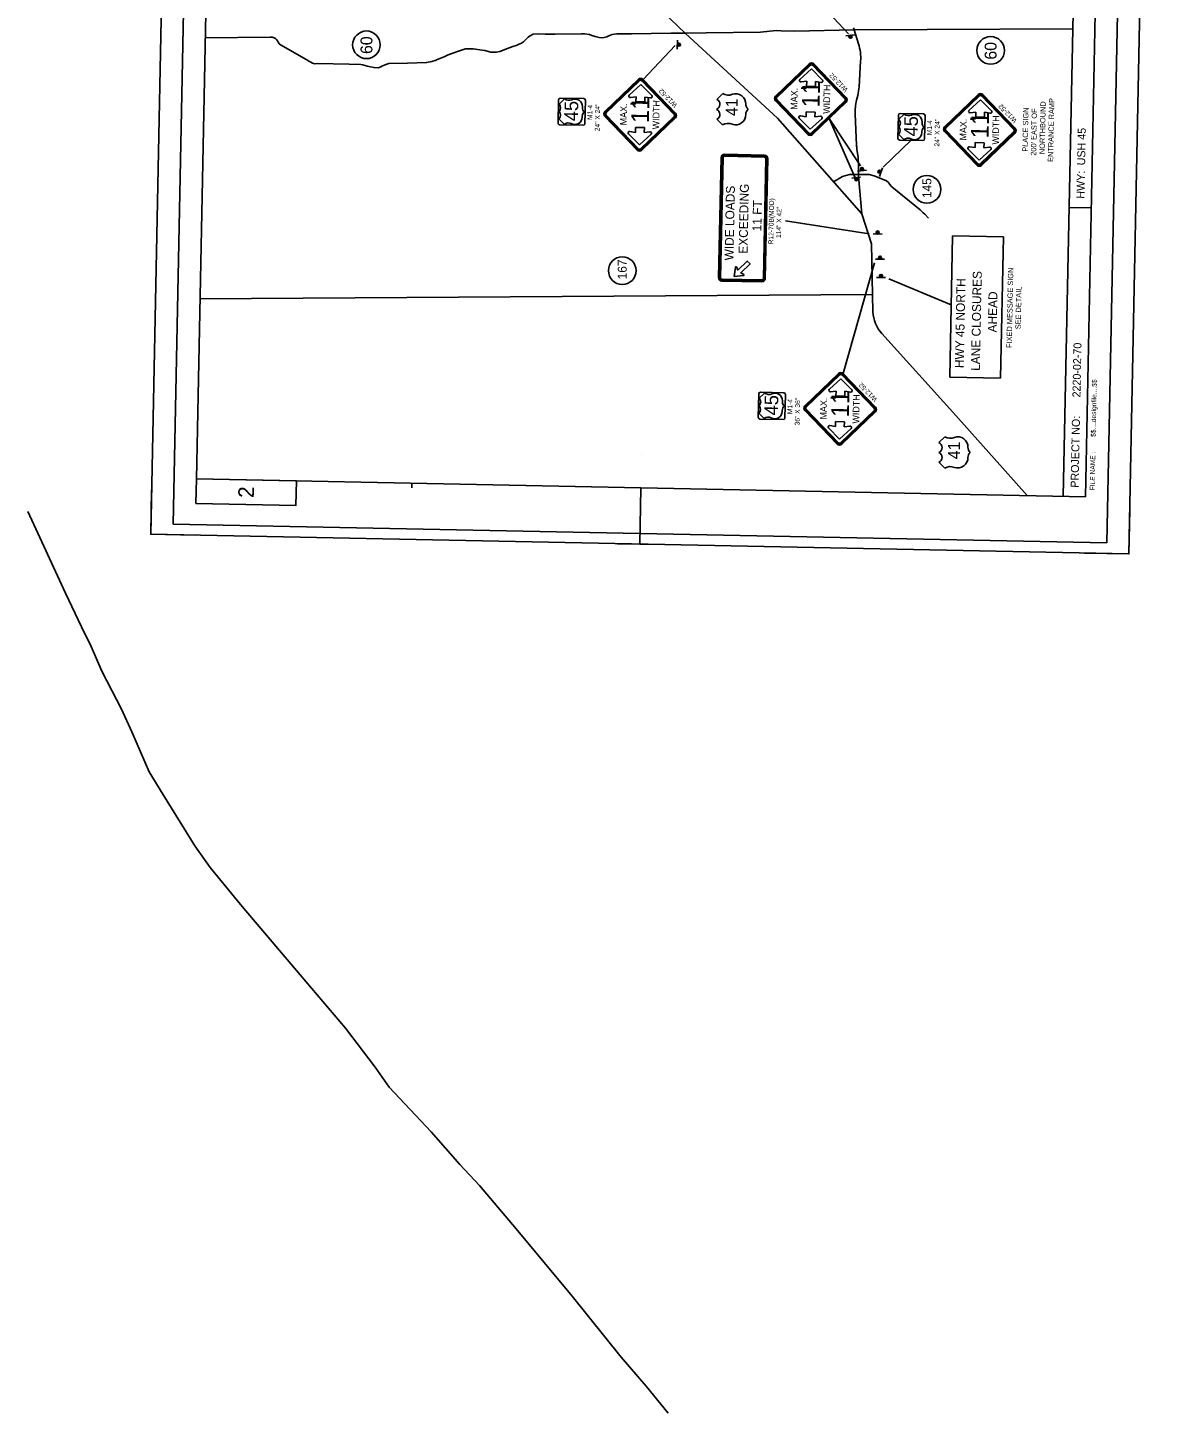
# Model space of a CAD drawing. Extents: x 2191881 to 2513407, y 347956 to 627029.
# Drawn here: x 2398895 to 2513407, y 347956 to 488157 of the extents above; entities that cross this region are included whole.
import ezdxf

# ---------------------------------------------------------------- set-up
doc = ezdxf.new("R2010")
doc.units = 0
for name, color, linetype in [('CA-TEXT', 7, 'Continuous'), ('Level 1', 7, 'Continuous'), ('Level 15', 7, 'Continuous'), ('Level 52', 7, 'Continuous'), ('P_RDWY_Text', 7, 'Continuous'), ('P_SGN_Cell', 7, 'Continuous'), ('P_TC', 7, 'Continuous'), ('PLT_Sheet_Border', 7, 'Continuous')]:
    doc.layers.add(name, color=color, linetype=linetype)

msp = doc.modelspace()

# ---------------------------------------------------------------- linework, layer by layer
at = {"layer": 'Level 1'}
msp.add_line((2458960, 353650), (2459055, 353554), dxfattribs=at)
for points in [[(2411176, 412871), (2409445, 416925), (2408371, 419215), (2406399, 423062), (2405327, 425534), (2404342, 427549), (2402731, 430937), (2398895, 439215)], [(2459055, 353554), (2458960, 353650), (2453998, 359805), (2448312, 366604), (2444611, 371014), (2442623, 373130), (2439733, 376438), (2435486, 380945), (2434044, 382964), (2431069, 386912), (2426465, 392333), (2420598, 399225), (2417349, 403176), (2415818, 405378), (2412581, 410605), (2411176, 412871)], [(2463712, 347956), (2461488, 350710), (2458960, 353650)]]:
    msp.add_lwpolyline(points, dxfattribs=at)
at = {"layer": 'Level 52'}
for p, q in [((2415960, 442501), (2418814, 584223)), ((2503692, 440734), (2506546, 582456)), ((2505942, 440689), (2508796, 582410)), ((2506530, 469933), (2504281, 469979)), ((2492210, 452806), (2492497, 467085)), ((2492497, 467085), (2497640, 466981)), ((2497352, 452703), (2497640, 466981)), ((2492210, 452806), (2497352, 452703)), ((2461019, 444970), (2461019, 444970)), ((2505942, 440689), (2415960, 442501)), ((2437780, 442062), (2437771, 441612)), ((2411346, 436901), (2411437, 441400)), ((2460836, 435904), (2460951, 441595)), ((2510326, 434907), (2510417, 439406)), ((2415845, 436810), (2411346, 436901)), ((2463086, 435859), (2458586, 435949)), ((2510326, 434907), (2505827, 434998))]:
    msp.add_line(p, q, dxfattribs=at)
msp.add_lwpolyline([(2415960, 442501), (2415910, 440027), (2426033, 439823), (2426083, 442297)], close=True, dxfattribs=at)
at = {"layer": 'P_RDWY_Text'}
for p, q in [((2465460, 487557), (2456867, 495857)), ((2476911, 492930), (2481949, 487544)), ((2476502, 487820), (2482538, 487931)), ((2482538, 487931), (2504645, 488037)), ((2482970, 486531), (2482538, 487931)), ((2465399, 487616), (2467564, 487634)), ((2474770, 478999), (2465460, 487556)), ((2467564, 487634), (2473055, 487719)), ((2473055, 487719), (2474646, 487864)), ((2474646, 487864), (2475155, 487837)), ((2475155, 487837), (2476502, 487820)), ((2433175, 486427), (2433175, 486427)), ((2461181, 482931), (2464428, 486351)), ((2496339, 485857), (2496339, 485857)), ((2483028, 482188), (2483182, 484758)), ((2468626, 480897), (2469223, 481495)), ((2482776, 480812), (2482897, 481312)), ((2470036, 479942), (2470036, 479942)), ((2468617, 478910), (2469214, 478313)), ((2483308, 469309), (2474770, 478999)), ((2480013, 478983), (2483175, 474166)), ((2480013, 478983), (2482609, 473023)), ((2482774, 476281), (2482640, 479422)), ((2485477, 474045), (2488300, 476763)), ((2482919, 475010), (2482810, 475859)), ((2482957, 473551), (2482959, 474361)), ((2481337, 473093), (2480447, 472557)), ((2482057, 473306), (2481337, 473093)), ((2483591, 473308), (2482057, 473306)), ((2483308, 469309), (2482974, 473131)), ((2489894, 471798), (2489894, 471798)), ((2484047, 467295), (2475591, 468618)), ((2484276, 466292), (2483309, 469309)), ((2484276, 466292), (2484412, 459415)), ((2484603, 464368), (2481422, 453164)), ((2459059, 463574), (2459059, 463574)), ((2492357, 460121), (2486044, 462734)), ((2484378, 461163), (2416327, 460717)), ((2492802, 448917), (2485332, 457203)), ((2492802, 448917), (2500028, 440808)), ((2491108, 446176), (2491706, 446773)), ((2492519, 445221), (2492519, 445221)), ((2491100, 444189), (2491697, 443591))]:
    msp.add_line(p, q, dxfattribs=at)
msp.add_lwpolyline([(2411346, 436901), (2414427, 589870), (2513407, 587876), (2510326, 434907)], close=True, dxfattribs=at)
for points in [[(2431411, 484483), (2428206, 484519), (2427964, 484517), (2427710, 484578), (2427531, 484661), (2427340, 484766), (2427139, 484923), (2424481, 486435), (2424343, 486539), (2424247, 486697), (2424161, 486834), (2424086, 486961), (2423969, 487076), (2423821, 487149), (2423621, 487190), (2423431, 487198), (2416859, 487135)], [(2431411, 484483), (2432595, 484439), (2432821, 484409), (2433256, 484281), (2433582, 484201), (2433942, 484114), (2434351, 484086), (2434468, 484121), (2434700, 484215), (2434716, 484249), (2435222, 484472), (2435447, 484525), (2437323, 484565), (2439257, 484622), (2439781, 484729), (2440221, 484876), (2440254, 484910), (2440595, 485031), (2440760, 485116), (2441026, 485219), (2441432, 485416), (2442379, 485745), (2443210, 486013), (2443985, 486023), (2444871, 485884), (2445139, 485837), (2445766, 485670), (2446316, 485677), (2446666, 485748), (2446957, 485852), (2447023, 485894), (2447446, 486049), (2447986, 486256), (2448426, 486403), (2448525, 486471), (2448874, 486592), (2449064, 486728), (2449534, 487209), (2449666, 487310), (2450056, 487490), (2450580, 487547), (2451273, 487506), (2452191, 487492), (2452274, 487493), (2454951, 487526)], [(2454951, 487526), (2455226, 487530), (2455752, 487470), (2455987, 487373), (2456330, 487260), (2456726, 487155), (2456954, 487125), (2457224, 487171), (2457498, 487241), (2457714, 487327), (2458054, 487465), (2458529, 487538), (2459715, 487539)], [(2459715, 487539), (2459997, 487542), (2463982, 487606), (2465414, 487601)], [(2483591, 473308), (2484050, 473288), (2484560, 473178), (2485817, 472669), (2486036, 472455), (2486096, 472322), (2486350, 472050), (2489223, 469719), (2489484, 469464), (2489502, 469414), (2489670, 469283), (2490065, 468893)]]:
    msp.add_lwpolyline(points, dxfattribs=at)
for centre in [(2433175, 486427), (2496339, 485857), (2489894, 471798), (2459059, 463574)]:
    msp.add_circle(centre, 1398, dxfattribs=at)
for centre, radius, start, end in [((2487316, 489403), 5000, 194.43825, 197.12806), ((2465460, 487557), 1, 225.991, 227.41449), ((2478191, 485058), 5000, 356.56138, 17.12806), ((2468395, 480400), 548, 293.11923, 65.07067), ((2469779, 482361), 1030, 237.31366, 294.1957), ((2470534, 480447), 1030, 357.80954, 108.90524), ((2478037, 482487), 5000, 346.39961, 356.56138), ((2468395, 479392), 548, 294.92933, 66.88077), ((2472309, 479363), 755, 133.77282, 178.75675), ((2472318, 480445), 755, 181.24325, 225.27704), ((2487635, 479636), 5000, 166.39961, 182.44488), ((2469770, 477446), 1030, 65.8043, 122.68634), ((2470525, 479360), 1030, 251.09476, 2.19046), ((2474770, 478999), 1, 41.38328, 47.41449), ((2487770, 476494), 5000, 182.44488, 187.30106), ((2477959, 474375), 5000, 359.83776, 7.30106), ((2487957, 473536), 5000, 179.83776, 184.64635), ((2483308, 469308), 1, 17.78377, 41.38328), ((2488317, 459741), 3918, 184.76287, 220.36638), ((2490877, 445679), 548, 293.11923, 65.07067), ((2492262, 447640), 1030, 237.31366, 294.1957), ((2493016, 445726), 1030, 357.80954, 108.90524), ((2490877, 444671), 548, 294.92933, 66.88077), ((2493007, 444639), 1030, 251.09476, 2.19046), ((2494792, 444642), 755, 133.77282, 178.75675), ((2494801, 445724), 755, 181.24325, 225.27704), ((2492253, 442725), 1030, 65.8043, 122.68634)]:
    msp.add_arc(centre, radius, start, end, dxfattribs=at)
at = {"layer": 'P_SGN_Cell'}
for p, q in [((2477046, 482910), (2478206, 483980)), ((2478206, 483980), (2479322, 482864)), ((2459775, 481336), (2460935, 482406)), ((2460935, 482406), (2462051, 481290)), ((2477732, 482733), (2477158, 482667)), ((2477721, 482232), (2477731, 482733)), ((2478631, 482715), (2478621, 482214)), ((2479201, 482625), (2478630, 482715)), ((2453227, 480957), (2452681, 480432)), ((2452799, 481030), (2455161, 480982)), ((2460461, 481159), (2459887, 481093)), ((2460450, 480658), (2460460, 481159)), ((2461360, 481141), (2461350, 480640)), ((2461930, 481051), (2461359, 481141)), ((2478621, 482214), (2477721, 482232)), ((2452579, 478503), (2452626, 480865)), ((2455031, 480063), (2455033, 480170)), ((2455302, 479629), (2455278, 478448)), ((2455326, 480810), (2455302, 479629)), ((2455326, 480810), (2455326, 480810)), ((2461350, 480640), (2460450, 480658)), ((2477659, 479144), (2477669, 479645)), ((2477669, 479645), (2478569, 479627)), ((2478569, 479627), (2478558, 479126)), ((2487174, 479486), (2489536, 479439)), ((2494150, 479792), (2495310, 480862)), ((2494836, 479615), (2494262, 479549)), ((2494825, 479114), (2494835, 479615)), ((2495310, 480863), (2496426, 479746)), ((2495735, 479597), (2495725, 479096)), ((2496305, 479508), (2495734, 479597)), ((2452650, 478932), (2453175, 478386)), ((2455106, 478283), (2452744, 478330)), ((2455012, 479099), (2455014, 479206)), ((2478083, 477879), (2476967, 478995)), ((2477089, 479234), (2477660, 479144)), ((2479243, 478949), (2478083, 477879)), ((2478558, 479126), (2479132, 479192)), ((2486954, 476959), (2487002, 479321)), ((2487602, 479413), (2487056, 478888)), ((2489406, 478520), (2489408, 478627)), ((2489677, 478085), (2489653, 476904)), ((2489701, 479266), (2489677, 478085)), ((2489701, 479266), (2489701, 479266)), ((2495725, 479096), (2494825, 479114)), ((2460812, 476305), (2459696, 477421)), ((2459818, 477660), (2460389, 477570)), ((2460388, 477570), (2460398, 478071)), ((2460398, 478071), (2461298, 478053)), ((2461972, 477375), (2460812, 476305)), ((2461286, 477552), (2461861, 477618)), ((2461298, 478053), (2461287, 477552)), ((2478083, 477879), (2478083, 477879)), ((2487026, 477389), (2487550, 476842)), ((2489481, 476739), (2487119, 476787)), ((2489387, 477555), (2489389, 477662)), ((2460812, 476305), (2460812, 476305)), ((2473453, 475263), (2469403, 475345)), ((2495188, 474761), (2494072, 475877)), ((2494193, 476116), (2494764, 476026)), ((2494763, 476026), (2494773, 476527)), ((2494773, 476527), (2495673, 476509)), ((2496347, 475832), (2495187, 474761)), ((2495662, 476008), (2496236, 476075)), ((2495673, 476509), (2495663, 476008)), ((2468814, 462866), (2469059, 475014)), ((2468899, 462865), (2469144, 475012)), ((2469011, 462862), (2469256, 475010)), ((2473449, 475066), (2469399, 475148)), ((2473451, 475179), (2469402, 475260)), ((2473342, 462775), (2473586, 474923)), ((2473454, 462773), (2473699, 474920)), ((2473539, 462771), (2473783, 474919)), ((2495187, 474761), (2495188, 474761)), ((2473198, 462637), (2469146, 462719)), ((2470621, 463947), (2470621, 463947)), ((2473194, 462441), (2469141, 462522)), ((2473196, 462525), (2469147, 462606)), ((2480017, 451568), (2481177, 452639)), ((2481177, 452639), (2482292, 451523)), ((2472820, 448735), (2472868, 451097)), ((2473469, 451190), (2472922, 450665)), ((2473040, 451263), (2475402, 451215)), ((2475273, 450296), (2475275, 450403)), ((2475567, 451043), (2475544, 449862)), ((2475567, 451043), (2475567, 451043)), ((2480702, 451392), (2480128, 451325)), ((2480691, 450891), (2480701, 451392)), ((2481591, 450873), (2480691, 450891)), ((2481601, 451374), (2481591, 450873)), ((2482171, 451284), (2481600, 451374)), ((2472892, 449165), (2473417, 448619)), ((2475253, 449332), (2475255, 449439)), ((2475544, 449862), (2475520, 448681)), ((2475348, 448516), (2472986, 448563)), ((2481054, 446537), (2479938, 447654)), ((2480059, 447892), (2480630, 447803)), ((2480629, 447803), (2480639, 448304)), ((2480639, 448304), (2481539, 448286)), ((2482214, 447608), (2481054, 446537)), ((2481528, 447785), (2482102, 447851)), ((2481539, 448286), (2481529, 447785)), ((2481054, 446537), (2481054, 446537))]:
    msp.add_line(p, q, dxfattribs=at)
for points in [[(2477976, 484514), (2474569, 481240)], [(2478036, 484452), (2474628, 481179)], [(2478110, 484374), (2474702, 481101)], [(2481585, 480965), (2478313, 484372)], [(2481662, 481040), (2478390, 484446)], [(2481724, 481099), (2478452, 484505)], [(2460705, 482940), (2457298, 479666)], [(2460765, 482878), (2457357, 479605)], [(2460839, 482800), (2457431, 479527)], [(2464314, 479391), (2461042, 482798)], [(2464391, 479466), (2461119, 482872)], [(2464453, 479525), (2461181, 482931)], [(2474698, 480897), (2477971, 477489)], [(2495080, 481396), (2491673, 478123)], [(2495140, 481334), (2491732, 478061)], [(2495214, 481257), (2491806, 477984)], [(2498689, 477848), (2495417, 481254)], [(2498766, 477922), (2495494, 481328)], [(2498828, 477981), (2495556, 481388)], [(2474559, 480763), (2477832, 477356)], [(2474621, 480823), (2477894, 477415)], [(2478176, 477485), (2481583, 480758)], [(2478250, 477408), (2481658, 480681)], [(2478309, 477346), (2481717, 480619)], [(2457288, 479189), (2460561, 475782)], [(2457350, 479249), (2460623, 475841)], [(2457427, 479323), (2460700, 475915)], [(2460905, 475911), (2464312, 479184)], [(2460979, 475834), (2464387, 479107)], [(2461038, 475772), (2464446, 479045)], [(2491663, 477645), (2494936, 474238)], [(2491725, 477705), (2494998, 474297)], [(2491802, 477779), (2495075, 474371)], [(2495280, 474367), (2498688, 477640)], [(2495354, 474290), (2498762, 477563)], [(2495413, 474228), (2498821, 477501)], [(2471356, 463181), (2471046, 463346), (2471989, 464252), (2471716, 464536), (2470773, 463630), (2470621, 463947)], [(2470621, 463947), (2470773, 463630), (2471716, 464536), (2471989, 464252), (2471046, 463346), (2471356, 463181)], [(2470514, 463930), (2470392, 462991), (2471335, 463076)], [(2471335, 463076), (2470392, 462991), (2470514, 463930)], [(2480947, 453172), (2477539, 449899)], [(2481006, 453110), (2477598, 449837)], [(2481080, 453033), (2477673, 449760)], [(2484555, 449624), (2481283, 453031)], [(2484633, 449698), (2481361, 453105)], [(2484694, 449758), (2481422, 453164)], [(2477529, 449422), (2480803, 446014)], [(2477591, 449481), (2480864, 446074)], [(2477669, 449556), (2480942, 446148)], [(2481146, 446144), (2484554, 449417)], [(2481220, 446066), (2484628, 449340)], [(2481280, 446005), (2484687, 449278)]]:
    msp.add_lwpolyline(points, dxfattribs=at)
for centre, radius, start, end in [((2478210, 484270), 337, 43.84622, 133.84622), ((2478210, 484270), 252, 43.84622, 133.84622), ((2478210, 484270), 145, 43.84622, 133.84622), ((2460939, 482696), 337, 43.84622, 133.84622), ((2460939, 482696), 252, 43.84622, 133.84622), ((2460939, 482696), 145, 43.84622, 133.84622), ((2477142, 482806), 141, 132.70164, 276.60197), ((2479223, 482764), 141, 261.07912, 44.97866), ((2452795, 480861), 169, 88.84622, 178.84622), ((2453677, 481557), 750, 233.11428, 291.9873), ((2454283, 480186), 750, 358.84616, 115.69277), ((2455157, 480814), 169, 358.84622, 88.84622), ((2459871, 481232), 141, 132.70164, 276.60197), ((2461951, 481190), 141, 261.07912, 44.97866), ((2474802, 480997), 337, 133.84433, 223.84622), ((2474802, 480997), 252, 133.84433, 223.84622), ((2474802, 480997), 145, 133.84433, 223.84622), ((2481483, 480862), 145, 313.85344, 44.49709), ((2481483, 480862), 252, 313.85344, 44.49709), ((2481483, 480862), 337, 313.85344, 44.49709), ((2495314, 481152), 337, 43.84622, 133.84622), ((2495314, 481152), 252, 43.84622, 133.84622), ((2495314, 481152), 145, 43.84622, 133.84622), ((2452275, 479315), 536, 314.41906, 43.27339), ((2452291, 480065), 536, 314.41906, 43.27339), ((2455556, 479192), 542, 126.05841, 178.50393), ((2455573, 480056), 542, 179.18852, 231.63404), ((2457531, 479423), 337, 133.84433, 223.84622), ((2457531, 479423), 252, 133.84433, 223.84622), ((2457531, 479423), 145, 133.84433, 223.84622), ((2464212, 479288), 337, 313.85344, 44.49709), ((2487170, 479317), 169, 88.84622, 178.84622), ((2494246, 479689), 141, 132.70164, 276.60197), ((2496327, 479647), 141, 261.07912, 44.97866), ((2452748, 478499), 169, 178.84622, 268.84622), ((2453603, 477770), 750, 67.71592, 124.79823), ((2454262, 479114), 750, 240.09813, 358.84629), ((2455110, 478452), 169, 268.84622, 358.84622), ((2464212, 479288), 145, 313.85344, 44.49709), ((2464212, 479288), 252, 313.85344, 44.49709), ((2477067, 479095), 141, 81.09048, 224.99081), ((2479148, 479053), 141, 312.71379, 96.61332), ((2486651, 477771), 536, 314.41906, 43.27339), ((2486666, 478521), 536, 314.41906, 43.27339), ((2488052, 480013), 750, 233.11428, 291.9873), ((2488658, 478642), 750, 358.84616, 115.69277), ((2489931, 477648), 542, 126.05841, 178.50393), ((2489948, 478512), 542, 179.18852, 231.63404), ((2489532, 479270), 169, 358.84622, 88.84622), ((2491907, 477879), 337, 133.84433, 223.84622), ((2459796, 477521), 141, 81.09048, 224.99081), ((2461877, 477479), 141, 312.71379, 96.61332), ((2478076, 477589), 337, 223.84622, 313.84622), ((2478076, 477589), 252, 223.84622, 313.84622), ((2478076, 477589), 145, 223.84622, 313.84622), ((2487123, 476955), 169, 178.84622, 268.84622), ((2487978, 476226), 750, 67.71592, 124.79823), ((2488637, 477570), 750, 240.09813, 358.84629), ((2489485, 476908), 169, 268.84622, 358.84622), ((2491907, 477879), 252, 133.84433, 223.84622), ((2491907, 477879), 145, 133.84433, 223.84622), ((2498587, 477745), 145, 313.85344, 44.49709), ((2498587, 477745), 252, 313.85344, 44.49709), ((2498587, 477745), 337, 313.85344, 44.49709), ((2460805, 476015), 337, 223.84622, 313.84622), ((2460805, 476015), 252, 223.84622, 313.84622), ((2460805, 476015), 145, 223.84622, 313.84622), ((2469397, 475007), 337, 88.84622, 178.84622), ((2494171, 475977), 141, 81.09048, 224.99081), ((2496252, 475935), 141, 312.71379, 96.61332), ((2469397, 475007), 253, 88.84622, 178.84622), ((2469397, 475007), 141, 88.84622, 178.84622), ((2473446, 474925), 141, 358.84622, 88.84622), ((2473446, 474925), 253, 358.84622, 88.84622), ((2473446, 474925), 337, 358.84622, 88.84622), ((2495180, 474472), 337, 223.84622, 313.84622), ((2495180, 474472), 252, 223.84622, 313.84622), ((2495180, 474472), 145, 223.84622, 313.84622), ((2469152, 462860), 337, 178.84622, 268.12534), ((2469152, 462860), 253, 178.84622, 268.84622), ((2469152, 462860), 141, 178.84622, 267.72942), ((2470570, 463923), 56.2, 25.66719, 172.58433), ((2470570, 463923), 56.2, 25.66719, 172.58433), ((2471330, 463132), 56.3, 275.10812, 62.02526), ((2471330, 463132), 56.3, 275.10812, 62.02526), ((2473201, 462778), 337, 268.84622, 358.84622), ((2473201, 462778), 253, 268.84622, 358.84622), ((2473201, 462778), 141, 268.84622, 358.84622), ((2481181, 452929), 337, 43.84622, 133.84622), ((2481181, 452929), 252, 43.84622, 133.84622), ((2481181, 452929), 145, 43.84622, 133.84622), ((2480112, 451465), 141, 132.70164, 276.60197), ((2482193, 451423), 141, 261.07912, 44.97866), ((2473037, 451094), 169, 88.84622, 178.84622), ((2472532, 450298), 536, 314.41906, 43.27339), ((2473919, 451790), 750, 233.11428, 291.9873), ((2474525, 450418), 750, 358.84616, 115.69277), ((2475815, 450288), 542, 179.18852, 231.63404), ((2475399, 451046), 169, 358.84622, 88.84622), ((2472989, 448732), 169, 178.84622, 268.84622), ((2472517, 449548), 536, 314.41906, 43.27339), ((2473845, 448003), 750, 67.71592, 124.79823), ((2474503, 449347), 750, 240.09813, 358.84629), ((2475797, 449425), 542, 126.05841, 178.50393), ((2475351, 448684), 169, 268.84622, 358.84622), ((2477773, 449656), 337, 133.84433, 223.84622), ((2477773, 449656), 252, 133.84433, 223.84622), ((2477773, 449656), 145, 133.84433, 223.84622), ((2484454, 449521), 145, 313.85344, 44.49709), ((2484454, 449521), 252, 313.85344, 44.49709), ((2484454, 449521), 337, 313.85344, 44.49709), ((2480037, 447753), 141, 81.09048, 224.99081), ((2482118, 447711), 141, 312.71379, 96.61332), ((2481046, 446248), 337, 223.84622, 313.84622), ((2481046, 446248), 252, 223.84622, 313.84622), ((2481046, 446248), 145, 223.84622, 313.84622)]:
    msp.add_arc(centre, radius, start, end, dxfattribs=at)
at = {"layer": 'P_TC'}
for p, q in [((2464632, 485991), (2464643, 486891)), ((2481699, 487351), (2482594, 487442)), ((2485385, 473962), (2485091, 473111)), ((2482283, 472944), (2483178, 473035)), ((2483774, 473747), (2482879, 473656)), ((2485351, 467269), (2484452, 467287)), ((2485589, 464721), (2484689, 464739)), ((2485691, 462876), (2484791, 462894))]:
    msp.add_line(p, q, dxfattribs=at)
for centre, radius in [((2464795, 486437), 158), ((2464795, 486437), 90), ((2482160, 487240), 158), ((2482160, 487240), 90), ((2482160, 487240), 22.5), ((2464795, 486437), 22.5), ((2483313, 473858), 158), ((2483313, 473858), 90), ((2483313, 473858), 22.5), ((2482744, 472832), 158), ((2482744, 472832), 90), ((2482744, 472832), 22.5), ((2485090, 473590), 158), ((2485090, 473590), 90), ((2485090, 473590), 22.5), ((2484907, 467435), 158), ((2484907, 467435), 90), ((2484907, 467435), 22.5), ((2485144, 464888), 158), ((2485144, 464888), 90), ((2485144, 464888), 22.5), ((2485247, 463043), 158), ((2485247, 463043), 90), ((2485247, 463043), 22.5)]:
    msp.add_circle(centre, radius, dxfattribs=at)
at = {"layer": 'PLT_Sheet_Border'}
for points in [[(2510326, 434907), (2513407, 587876), (2414427, 589870), (2411346, 436901)], [(2508098, 436032), (2511097, 584952), (2416617, 586855), (2413617, 437935)]]:
    msp.add_lwpolyline(points, close=True, dxfattribs=at)

# ---------------------------------------------------------------- texts
at = {"layer": 'CA-TEXT'}
for s, p in [('PLACE SIGN', (2500089, 475605)), ("200' EAST OF", (2500945, 475201)), ('NORTHBOUND', (2501813, 475357)), ('ENTRANCE RAMP', (2502661, 474571)), ('FIXED MESSAGE SIGN', (2498478, 455752)), ('SEE DETAIL', (2499380, 457641))]:
    msp.add_text(s, height=540, rotation=88.84622, dxfattribs=at).set_placement(p)
at = {"layer": 'Level 15'}
for s, p in [('HWY 45 NORTH', (2493617, 453703)), ('LANE CLOSURES', (2495242, 453429)), ('AHEAD', (2496951, 457318))]:
    msp.add_text(s, height=900, rotation=88.84622, dxfattribs=at).set_placement(p)
at = {"layer": 'Level 52'}
for s, height, rotation, p in [('USH 45          ', 810, 88.84622, (2505897, 474222)), ('HWY:', 810, 88.84622, (2505829, 470848)), ('2220-02-70', 810, 88.84622, (2505424, 450737)), ('$$....designfile....$$', 486, 88.84621, (2506964, 446745)), ('PROJECT NO:', 810, 88.84622, (2505240, 441603)), ('FILE NAME :', 486, 88.84622, (2506855, 441346)), ('2', 1575, 88.84622, (2421772, 440557))]:
    msp.add_text(s, height=height, rotation=rotation, dxfattribs=at).set_placement(p)
at = {"layer": 'P_RDWY_Text'}
for s, height, p in [('60', 1200, (2433775, 485496)), ('60', 1200, (2496939, 484926)), ('41', 1200, (2470742, 479215)), ('145', 900, (2490344, 470920)), ('167', 900, (2459509, 462695)), ('41', 1200, (2493225, 444493))]:
    msp.add_text(s, height=height, rotation=90, dxfattribs=at).set_placement(p)
at = {"layer": 'P_SGN_Cell'}
for s, height, rotation, p in [('11', 1800, 88.84622, (2479026, 480071)), ('WIDTH', 675, 88.84622, (2480062, 479439)), ('W12-52', 486, 133.84622, (2481938, 481926)), ('11', 1800, 88.84622, (2461755, 478497)), ('W12-52', 486, 133.84622, (2464667, 480352)), ('MAX.', 675, 88.84622, (2476771, 479851)), ("'", 1800, 88.84622, (2478961, 481787)), ('45', 1380, 88.84622, (2454576, 478689)), ('M1-4', 486, 88.84622, (2456012, 478820)), ('24" X 24"', 486, 88.84622, (2456761, 477678)), ('MAX.', 675, 88.84622, (2459500, 478277)), ("'", 1800, 88.84622, (2461690, 480213)), ('WIDTH', 675, 88.84622, (2462791, 477865)), ('11', 1800, 88.84622, (2496130, 476954)), ('W12-52', 486, 133.84622, (2499042, 478808)), ('45', 1380, 88.84622, (2488951, 477145)), ('M1-4', 486, 88.84622, (2490387, 477276)), ('24" X 24"', 486, 88.84622, (2491136, 476134)), ('MAX.', 675, 88.84622, (2493875, 476734)), ("'", 1800, 88.84622, (2496065, 478669)), ('WIDTH', 675, 88.84622, (2497166, 476321)), ('WIDE LOADS', 900, 88.84622, (2470312, 464603)), ('EXCEEDING', 900, 88.84622, (2471733, 465283)), ('11 FT', 900, 88.84622, (2473133, 467544)), ('R12-70B(MOD)', 486, 88.84622, (2474334, 466237)), ('114" X 42"', 486, 88.84622, (2475119, 466872)), ('W12-52', 486, 133.84622, (2484908, 450584)), ('45', 1380, 88.84622, (2474818, 448921)), ('M1-4', 486, 88.84622, (2476254, 449052)), ('36" X 36"', 486, 88.84622, (2477002, 447910)), ('MAX.', 675, 88.84622, (2479742, 448510)), ("'", 1800, 88.84622, (2481932, 450445)), ('11', 1800, 88.84622, (2481996, 448730)), ('WIDTH', 675, 88.84622, (2483033, 448097))]:
    msp.add_text(s, height=height, rotation=rotation, dxfattribs=at).set_placement(p)

doc.saveas('drawing.dxf')
